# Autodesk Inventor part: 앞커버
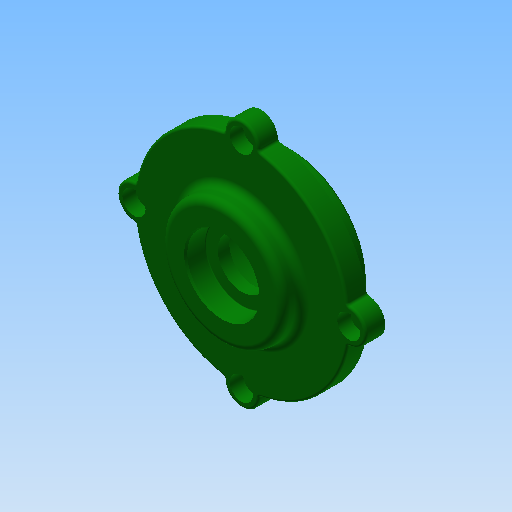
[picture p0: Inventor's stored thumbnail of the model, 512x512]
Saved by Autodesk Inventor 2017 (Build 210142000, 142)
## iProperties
Created: 2016-05
Part Number: 앞커버
Document SubType Name: Modeling
Designer: mduedu
Density: 2.71 g/cm^3
Material: 알루미늄 6061
Appearance: 진녹색
Author: mduedu
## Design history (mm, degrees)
sketch "스케치1"
  geometry: C1 r 32 at (0, 0); C2 r 44 at (0, 0); 1 further point
  constraints: 2 centre point, 2 coincident
  dimensions: "d33" = 88 diameter of C2; "d34" = 64 diameter of C1
extrude "돌출1" new body sketch "스케치1" distance "d0" = 8; taper "d1" = 0 deg
extrude "돌출2" join sketch "스케치1" distance "d2" = 8; taper "d3" = 0 deg; dims "d35" = 12, "d36" = 0
sketch "스케치6"
  geometry: C1 r 25 at (0, 0); 2 further points
  constraints: 2 coincident, 1 centre point
  dimensions: "d42" = 50 diameter of C1
extrude "돌출4" join sketch "스케치6" distance "d43" = 8; taper "d44" = 0 deg
sketch "스케치9"
  geometry: C1 r 7 at (0, 44); 2 further points
  constraints: 2 vertical alignment, 1 centre point, 1 other
  dimensions: "d70" = 14 diameter of C1
extrude "돌출5" join sketch "스케치9" stored distance "d71" = 10; taper "d72" = 0 deg
fillet "모깎기9" dims "d76" = 1
sketch "스케치10"
  geometry: C1 r 25 at (0, 0) reference; A1 r 1 centre (-44.284, 7.995) between (-44.249, 6.996) and (-43.3, 7.817) reference; A2 r 7 centre (-44, 0) between (-44.249, 6.996) and (-44.249, -6.996) reference; A3 r 1 centre (-44.284, -7.995) between (-43.3, -7.817) and (-44.249, -6.996) reference; A4 r 44 centre (0, 0) between (-43.3, -7.817) and (-7.817, -43.3) reference; A5 r 1 centre (-7.995, -44.284) between (-6.996, -44.249) and (-7.817, -43.3) reference; A6 r 7 centre (0, -44) between (-6.996, -44.249) and (6.996, -44.249) reference; A7 r 1 centre (7.995, -44.284) between (7.817, -43.3) and (6.996, -44.249) reference; A8 r 1 centre (7.995, 44.284) between (6.996, 44.249) and (7.817, 43.3) reference; A9 r 7 centre (0, 44) between (6.996, 44.249) and (-6.996, 44.249) reference; A10 r 1 centre (-7.995, 44.284) between (-7.817, 43.3) and (-6.996, 44.249) reference; A11 r 7 centre (44, 0) between (44.249, -6.996) and (44.249, 6.996) reference; A12 r 44 centre (0, 0) between (-7.817, 43.3) and (-43.3, 7.817) reference; A13 r 44 centre (0, 0) between (7.817, -43.3) and (43.3, -7.817) reference; A14 r 1 centre (44.284, -7.995) between (44.249, -6.996) and (43.3, -7.817) reference; A15 r 1 centre (44.284, 7.995) between (43.3, 7.817) and (44.249, 6.996) reference; A16 r 44 centre (0, 0) between (43.3, 7.817) and (7.817, 43.3) reference; 4 further points
  constraints: 3 coincident
hole "구멍3" sketch "스케치10" at (0, 44), (-44, 0), (0, -44), (44, 0) diameter "d77" = 5.5; stored, may be unused: countersink angle "d81" = 90 deg, drill point angle "d83" = 118 deg; dims "d78" = 6, "d79" = 9.5, "d80" = 5.4, "d82" = 8
fillet "모깎기10" dims "d84" = 1
fillet "모깎기7" dims "d68" = 3
fillet "모깎기8" dims "d69" = 3
sketch "스케치4"
  geometry: L1 (0, -12)-(0, 16); L2 (-20, -12)-(-20, 0); L3 (-20, 0)-(-15, 0); L4 (-15, 0)-(-15, 3); L5 (-15, 3)-(-10, 3); L6 (-10, 3)-(-10, 7.7); L7 (-10, 7.7)-(-15, 7.7); L8 (-15, 7.7)-(-15, 16); L9 (32, -12)-(-32, -12) reference; L10 (25, 16)-(-25, 16) reference; 1 further point
  constraints: 16 end point, 6 parallel, 3 point on line, 2 midpoint, 1 perpendicular, 1 vertical
  dimensions: "d15" = 40 diameter of L2 L1; "d16" = 30 diameter of L8 L1; "d18" = 12 distance of L2.start L2.end; "d19" = 3 distance of L3.end L4.end; "d20" = 30 diameter of L4 L1; "d21" = 20 diameter of L6 L1; "d45" = 8.3 distance of L7.end L8.end
revolve "회전1" sketch "스케치4" stored, may be unused: angle "d22" = 90 deg
fillet "모깎기2" dims "d23" = 3
fillet "모깎기3" dims "d24" = 0.3
chamfer "모따기2" distance "d46" = 1; stored, may be unused: second distance "d47" = 2, angle "d48" = 45 deg
chamfer "모따기3" distance "d64" = 0.8; stored, may be unused: second distance "d65" = 2, angle "d66" = 30 deg
node "솔리드1"
pattern_circular "원형 패턴1" dims angle "d74" = 360 deg
node "투영된 루프1"
